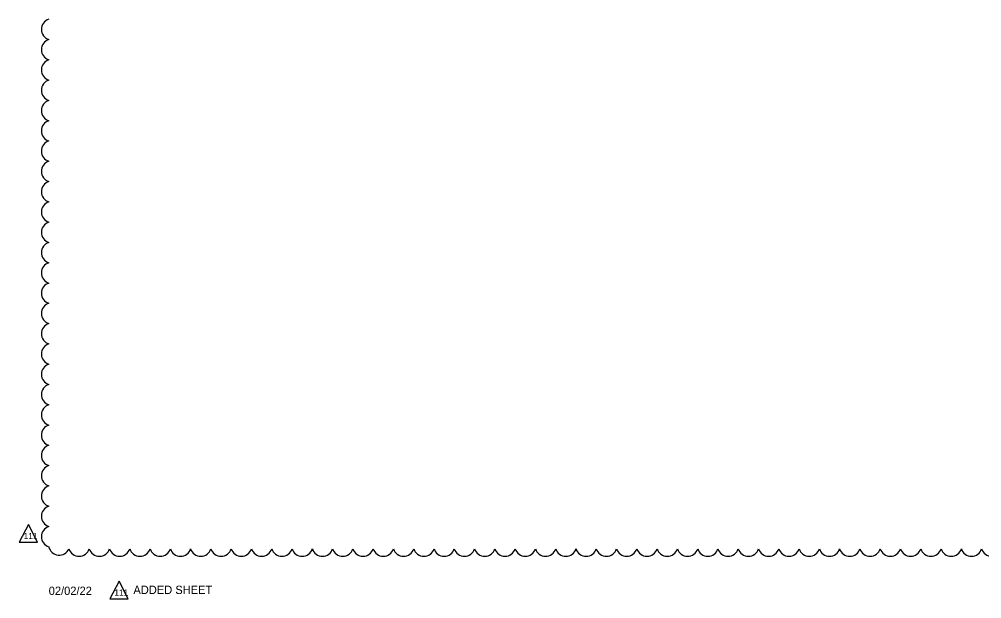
# Model space of a CAD drawing. Extents: x -811 to -790, y -2284 to -2178.
# Drawn here: x -811.04 to -802.91, y -2245.1 to -2240.21 of the extents above; entities that cross this region are included whole.
import ezdxf

# ---------------------------------------------------------------- set-up
doc = ezdxf.new("R2010")
doc.units = 0
doc.layers.add('TextMisc', color=7, linetype='Continuous')
doc.layers.add('TextTitle', color=7, linetype='Continuous')

msp = doc.modelspace()

# ---------------------------------------------------------------- linework, layer by layer
at = {"layer": 'TextMisc'}
for points in [[(-810.9581, -2244.4756), (-811.0351, -2244.624), (-810.8811, -2244.624)], [(-810.1928, -2244.9521), (-810.2698, -2245.1004), (-810.1158, -2245.1004)]]:
    msp.add_lwpolyline(points, close=True, dxfattribs=at)
at = {"layer": 'TextTitle'}
for centre, radius, start, end in [((-810.7588, -2240.2985), 0.0897, 107.5, 252.5), ((-810.7588, -2240.4696), 0.0897, 107.5, 252.5), ((-810.7588, -2240.6407), 0.0897, 107.5, 252.5), ((-810.7588, -2240.8118), 0.0897, 107.5, 252.5), ((-810.7588, -2240.983), 0.0897, 107.5, 252.5), ((-810.7588, -2241.1541), 0.0897, 107.5, 252.5), ((-810.7588, -2241.3252), 0.0897, 107.5, 252.5), ((-810.7588, -2241.4963), 0.0897, 107.5, 252.5), ((-810.7588, -2241.6675), 0.0897, 107.5, 252.5), ((-810.7588, -2241.8386), 0.0897, 107.5, 252.5), ((-810.7588, -2242.0097), 0.0897, 107.5, 252.5), ((-810.7588, -2242.1808), 0.0897, 107.5, 252.5), ((-810.7588, -2242.3519), 0.0897, 107.5, 252.5), ((-810.7588, -2242.5231), 0.0897, 107.5, 252.5), ((-810.7588, -2242.6942), 0.0897, 107.5, 252.5), ((-810.7588, -2242.8653), 0.0897, 107.5, 252.5), ((-810.7588, -2243.0364), 0.0897, 107.5, 252.5), ((-810.7588, -2243.2076), 0.0897, 107.5, 252.5), ((-810.7588, -2243.3787), 0.0897, 107.5, 252.5), ((-810.7588, -2243.5498), 0.0897, 107.5, 252.5), ((-810.7588, -2243.7209), 0.0897, 107.5, 252.5), ((-810.7588, -2243.892), 0.0897, 107.5, 252.5), ((-810.7588, -2244.0632), 0.0897, 107.5, 252.5), ((-810.7588, -2244.2343), 0.0897, 107.5, 252.5), ((-810.7588, -2244.4054), 0.0897, 107.5, 252.5), ((-810.7588, -2244.5765), 0.0897, 107.5, 252.5), ((-810.698, -2244.6438), 0.0896, 191.74536, 336.74536), ((-810.5301, -2244.6523), 0.0897, 197.5, 342.5), ((-810.359, -2244.6523), 0.0897, 197.5, 342.5), ((-810.1879, -2244.6523), 0.0897, 197.5, 342.5), ((-810.0167, -2244.6523), 0.0897, 197.5, 342.5), ((-809.8456, -2244.6523), 0.0897, 197.5, 342.5), ((-809.6745, -2244.6523), 0.0897, 197.5, 342.5), ((-809.5034, -2244.6523), 0.0897, 197.5, 342.5), ((-809.3323, -2244.6523), 0.0897, 197.5, 342.5), ((-809.1611, -2244.6523), 0.0897, 197.5, 342.5), ((-808.99, -2244.6523), 0.0897, 197.5, 342.5), ((-808.8189, -2244.6523), 0.0897, 197.5, 342.5), ((-808.6478, -2244.6523), 0.0897, 197.5, 342.5), ((-808.4766, -2244.6523), 0.0897, 197.5, 342.5), ((-808.3055, -2244.6523), 0.0897, 197.5, 342.5), ((-808.1344, -2244.6523), 0.0897, 197.5, 342.5), ((-807.9633, -2244.6523), 0.0897, 197.5, 342.5), ((-807.7921, -2244.6523), 0.0897, 197.5, 342.5), ((-807.621, -2244.6523), 0.0897, 197.5, 342.5), ((-807.4499, -2244.6523), 0.0897, 197.5, 342.5), ((-807.2788, -2244.6523), 0.0897, 197.5, 342.5), ((-807.1077, -2244.6523), 0.0897, 197.5, 342.5), ((-806.9365, -2244.6523), 0.0897, 197.5, 342.5), ((-806.7654, -2244.6523), 0.0897, 197.5, 342.5), ((-806.5943, -2244.6523), 0.0897, 197.5, 342.5), ((-806.4232, -2244.6523), 0.0897, 197.5, 342.5), ((-806.252, -2244.6523), 0.0897, 197.5, 342.5), ((-806.0809, -2244.6523), 0.0897, 197.5, 342.5), ((-805.9098, -2244.6523), 0.0897, 197.5, 342.5), ((-805.7387, -2244.6523), 0.0897, 197.5, 342.5), ((-805.5676, -2244.6523), 0.0897, 197.5, 342.5), ((-805.3964, -2244.6523), 0.0897, 197.5, 342.5), ((-805.2253, -2244.6523), 0.0897, 197.5, 342.5), ((-805.0542, -2244.6523), 0.0897, 197.5, 342.5), ((-804.8831, -2244.6523), 0.0897, 197.5, 342.5), ((-804.7119, -2244.6523), 0.0897, 197.5, 342.5), ((-804.5408, -2244.6523), 0.0897, 197.5, 342.5), ((-804.3697, -2244.6523), 0.0897, 197.5, 342.5), ((-804.1986, -2244.6523), 0.0897, 197.5, 342.5), ((-804.0275, -2244.6523), 0.0897, 197.5, 342.5), ((-803.8563, -2244.6523), 0.0897, 197.5, 342.5), ((-803.6852, -2244.6523), 0.0897, 197.5, 342.5), ((-803.5141, -2244.6523), 0.0897, 197.5, 342.5), ((-803.343, -2244.6523), 0.0897, 197.5, 342.5), ((-803.1718, -2244.6523), 0.0897, 197.5, 342.5), ((-803.0007, -2244.6523), 0.0897, 197.5, 342.5), ((-802.8296, -2244.6523), 0.0897, 197.5, 342.5)]:
    msp.add_arc(centre, radius, start, end, dxfattribs=at)

# ---------------------------------------------------------------- texts
at = {"layer": 'TextMisc'}
for p in [(-810.9978, -2244.5976), (-810.2325, -2245.074)]:
    msp.add_text('111', height=0.0525, rotation=360, dxfattribs=at).set_placement(p)
at = {"layer": 'TextTitle'}
for s, p in [('02/02/22', (-810.7866, -2245.0683)), ('ADDED SHEET', (-810.0721, -2245.0602))]:
    msp.add_text(s, height=0.07, rotation=0, dxfattribs=at).set_placement(p)

doc.saveas('drawing.dxf')
